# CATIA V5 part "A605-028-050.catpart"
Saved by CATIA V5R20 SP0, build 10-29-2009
Part number: A605-028-050
Source: Unknown
Property "A": "0.000"
Property "ARTICLENO": "A605-028-050"
Property "BOMINFO": "A605-028-050"
Property "CODE": "A605-028-050"
Property "D": "9.000"
Property "FORM": "A"
Property "L": "50.000"
Property "L1": "20.000"
Property "LINA": "A605-028-050"
Property "NB": "A605-028-050"
Property "NBSYN": "$CODE."
Property "NN": "A605"
Property "NT": "Wear Plates, self-lubricating"
Property "SCREW": "2*M8X10"
Property "SUPPLIER": "CF"
Property "W": "28.000"
Bounding box of the stored display mesh (mm): x -28 to 0, y 0 to 5, z -50 to 0
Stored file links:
  C:\Users\Utente\Desktop\3D files A605\A605-028-050.catpart
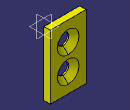
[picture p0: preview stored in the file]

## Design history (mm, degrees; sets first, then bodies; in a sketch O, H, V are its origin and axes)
Body1 "Geometry.1" (main body)
  Solid1 "A605-028-050.catpart": solid without history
